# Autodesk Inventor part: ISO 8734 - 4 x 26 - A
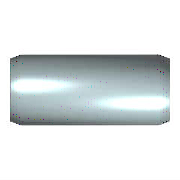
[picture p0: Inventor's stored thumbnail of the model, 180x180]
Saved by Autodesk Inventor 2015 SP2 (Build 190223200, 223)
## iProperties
IsCustomPart: 0
Created: 2012-02
Part Number: ISO 8734 - 4 x 26 - A
Material: Stahl
Description: Zylinderstift
Document SubType Name: Modeling
Standard: ISO 8734
Designer: rYan
Standards Organization: DIN
Language: de-DE
Size Designation: 4 x 26 - A
Categories: <MemberInstance><Categories><Category DisplayName="Verbindungselemente" InternalName="e4da775c-781d-43d5-af7c-5136215cf5a6" Mnemonic="FSTN"><Category DisplayNam
Density: 7.85 g/cm^3
Mass: 2.5546 g
Surface Area: 3.47662 cm^2
Volume: 0.325427 cm^3
Appearance: Platte
Author: rYan
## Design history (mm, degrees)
sketch "Skizze"
  geometry: C1 r 2 at (0, 0); 1 further point
  constraints: 1 centre point, 1 coincident
  dimensions: "d1" = 4 diameter of C1 (= NND)
extrude "Körper" new body sketch "Skizze" distance "d2" = 26 (= NLG); taper "d3" = 0 deg
body "Solid1"
chamfer "Fase1" distance "d4" = 0.63 (= PHH); stored, may be unused: angle "d5" = 15 deg (= FAWI), second distance "d11" = 0.63 (= PHH)
chamfer "Fase2" distance "d8" = 0.63 (= PHH); stored, may be unused: angle "d9" = 15 deg (= FAWI), second distance "d12" = 0.63 (= PHH)
other parameters: "NND" = 4 [user parameter; used in 1 equation term], "NLG" = 26 [user parameter; used in 1 equation term], "PHH" = 0.63 [user parameter; used in 5 equation terms], "FAWI" = 15 deg [user parameter; used in 2 equation terms], "d13" = 0, "d15" = 0, "d16" = 0, "PHH2" = 0.63 (= PHH) [user parameter], "FAWI2" = 15 deg [user parameter]
